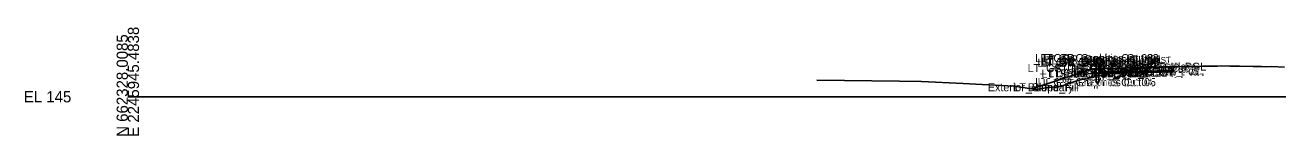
# Model space of a CAD drawing. Extents: x -26 to 603, y -10 to 9526.
# Drawn here: x -25.7 to 287.5, y 2490.3 to 2517.3 of the extents above; entities that cross this region are included whole.
import ezdxf

# ---------------------------------------------------------------- set-up
doc = ezdxf.new("R2010")
doc.units = 0
for name, color, linetype in [('Default', 7, 'Continuous'), ('Exist Cross Section Cell', 7, 'Continuous'), ('Exist XS Ground Line', 7, 'Continuous'), ('Prop CMT Guardrail Graphics', 7, 'Continuous'), ('Prop CMT Pvmt Course 1', 7, 'Continuous'), ('Prop CMT Pvmt Course 2', 7, 'Continuous'), ('Prop CMT Pvmt Course 3', 7, 'Continuous'), ('Prop CMT Pvmt Surface', 7, 'Continuous'), ('Prop CMT Pvmt Surface Shoulder', 7, 'Continuous'), ('Prop CMT Shld Paved Course 1', 7, 'Continuous'), ('Prop CMT Shld Paved Course 2', 7, 'Continuous'), ('Prop CMT Shld Paved Course 3', 7, 'Continuous'), ('Prop CMT Slope Grass', 7, 'Continuous'), ('Prop CMT Subgrade Earthwork', 7, 'Continuous'), ('Prop XS SE Text', 7, 'Continuous'), ('Prop XS Side Slope Text', 7, 'Continuous'), ('Scratch_Level_2', 7, 'Continuous')]:
    doc.layers.add(name, color=color, linetype=linetype)

msp = doc.modelspace()

# ---------------------------------------------------------------- linework, layer by layer
at = {"layer": 'Exist Cross Section Cell'}
msp.add_line((0, 2500), (300, 2500), dxfattribs=at)
at = {"layer": 'Exist XS Ground Line'}
for p, q in [((244.74, 2505.65), (252.04, 2507.04)), ((252.04, 2507.04), (252.56, 2507.07)), ((252.56, 2507.07), (253.09, 2507.09)), ((253.09, 2507.09), (254.92, 2507.17)), ((254.92, 2507.17), (255.92, 2507.22)), ((255.92, 2507.22), (258.43, 2507.35)), ((258.43, 2507.35), (258.99, 2507.48)), ((258.99, 2507.48), (259.8, 2507.44)), ((259.8, 2507.44), (260.5, 2507.49)), ((260.5, 2507.49), (261.3, 2507.51)), ((261.3, 2507.51), (261.88, 2507.48)), ((261.88, 2507.48), (262.47, 2507.48)), ((262.47, 2507.48), (264.8, 2507.54)), ((264.8, 2507.54), (266.91, 2507.58)), ((266.91, 2507.58), (268.66, 2507.61)), ((268.66, 2507.61), (272.4, 2507.66)), ((272.4, 2507.66), (273.44, 2507.72)), ((273.44, 2507.72), (275.47, 2507.67)), ((275.47, 2507.67), (277.58, 2507.63)), ((277.58, 2507.63), (277.89, 2507.63)), ((277.89, 2507.63), (281.35, 2507.58)), ((281.35, 2507.58), (283.38, 2507.53)), ((283.38, 2507.53), (284.38, 2507.49)), ((284.38, 2507.49), (285.9, 2507.53)), ((285.9, 2507.53), (289.13, 2507.37)), ((172.28, 2504.14), (192.92, 2503.92)), ((192.92, 2503.92), (198.38, 2503.81)), ((198.38, 2503.81), (208.83, 2503.28)), ((208.83, 2503.28), (221.57, 2502.63)), ((221.57, 2502.63), (223.84, 2502.34)), ((230.07, 2502.3), (233.26, 2502.59)), ((233.26, 2502.59), (235.18, 2503.28)), ((235.18, 2503.28), (238.35, 2504.34)), ((238.35, 2504.34), (244.74, 2505.65)), ((223.84, 2502.34), (226.91, 2501.79)), ((226.91, 2501.79), (230.07, 2502.3))]:
    msp.add_line(p, q, dxfattribs=at)
at = {"layer": 'Prop CMT Guardrail Graphics'}
for points in [[(242.04, 2503.57), (242.04, 2509.57)], [(242.04, 2509.57), (243.38, 2509.57), (243.65, 2509.28)], [(243.65, 2509.28), (243.38, 2508.98)], [(243.38, 2508.98), (243.65, 2508.69)], [(243.65, 2508.69), (243.38, 2508.4), (242.71, 2508.4)], [(242.71, 2508.4), (242.71, 2503.57)], [(242.71, 2503.57), (242.04, 2503.57)]]:
    msp.add_lwpolyline(points, dxfattribs=at)
at = {"layer": 'Prop CMT Pvmt Course 1'}
for points in [[(261.3, 2507.51), (253.1, 2507.3)], [(253.1, 2507.3), (253.1, 2506.39)], [(253.1, 2506.39), (261.3, 2506.59)], [(261.3, 2506.59), (261.3, 2507.51)]]:
    msp.add_lwpolyline(points, dxfattribs=at)
at = {"layer": 'Prop CMT Pvmt Course 2'}
for points in [[(261.3, 2506.59), (253.1, 2506.39)], [(253.1, 2506.39), (253.1, 2506.05)], [(253.1, 2506.05), (261.3, 2506.26)], [(261.3, 2506.26), (261.3, 2506.59)]]:
    msp.add_lwpolyline(points, dxfattribs=at)
at = {"layer": 'Prop CMT Pvmt Course 3'}
for points in [[(261.3, 2506.26), (253.1, 2506.05)], [(253.1, 2506.05), (261.3, 2506.26)], [(253.1, 2506.05), (253.1, 2506.05)], [(261.3, 2506.26), (261.3, 2506.26)]]:
    msp.add_lwpolyline(points, dxfattribs=at)
at = {"layer": 'Prop CMT Pvmt Surface'}
msp.add_lwpolyline([(261.3, 2507.51), (253.1, 2507.3)], dxfattribs=at)
at = {"layer": 'Prop CMT Pvmt Surface Shoulder'}
msp.add_lwpolyline([(253.1, 2507.3), (243.65, 2507.07)], dxfattribs=at)
at = {"layer": 'Prop CMT Shld Paved Course 1'}
for p, q in [((243.65, 2507.07), (242.71, 2506.13)), ((253.1, 2507.3), (247.64, 2507.17))]:
    msp.add_line(p, q, dxfattribs=at)
for points in [[(246.7, 2506.23), (253.1, 2506.39)], [(253.1, 2506.39), (253.1, 2507.3)]]:
    msp.add_lwpolyline(points, dxfattribs=at)
at = {"layer": 'Prop CMT Shld Paved Course 2'}
for p, q in [((242.71, 2506.13), (242.37, 2505.79)), ((253.1, 2506.39), (242.71, 2506.13))]:
    msp.add_line(p, q, dxfattribs=at)
for points in [[(246.36, 2505.89), (253.1, 2506.05)], [(253.1, 2506.05), (253.1, 2506.39)]]:
    msp.add_lwpolyline(points, dxfattribs=at)
at = {"layer": 'Prop CMT Shld Paved Course 3'}
for points in [[(253.1, 2506.05), (246.36, 2505.89), (245.86, 2505.87)], [(245.86, 2505.87), (253.1, 2506.05)], [(245.86, 2505.87), (245.86, 2505.87)], [(253.1, 2506.05), (253.1, 2506.05)]]:
    msp.add_lwpolyline(points, dxfattribs=at)
at = {"layer": 'Prop CMT Slope Grass'}
for points in [[(240.65, 2506.83), (226.02, 2501.95)], [(243.65, 2507.07), (240.65, 2506.83)]]:
    msp.add_lwpolyline(points, dxfattribs=at)
at = {"layer": 'Prop CMT Subgrade Earthwork'}
for points in [[(245.86, 2505.87), (237.13, 2505.65)], [(253.1, 2506.05), (245.86, 2505.87)], [(261.3, 2506.26), (253.1, 2506.05)]]:
    msp.add_lwpolyline(points, dxfattribs=at)

# ---------------------------------------------------------------- texts
at = {"layer": 'Default'}
msp.add_text('-', height=0.0001, dxfattribs=at).set_placement((0, 2500))
msp.add_text('-', height=0.0001, dxfattribs=at).set_placement((0, 2500))
msp.add_text('-', height=0.0001, dxfattribs=at).set_placement((0, 2500))
msp.add_text('-', height=0.0001, dxfattribs=at).set_placement((0, 2500))
at = {"layer": 'Exist Cross Section Cell'}
for s, p in [('N 662328.0085', (0, 2490)), ('E 2245945.4838', (2.8, 2490))]:
    msp.add_text(s, height=2.8, rotation=90, dxfattribs=at).set_placement(p)
msp.add_text('EL 145', height=2.8, dxfattribs=at).set_placement((-26, 2498.6))
at = {"layer": 'Prop XS SE Text'}
msp.add_text('EXIST', height=1.5, rotation=1.4321, dxfattribs=at).set_placement((254.98, 2508.35))
at = {"layer": 'Prop XS Side Slope Text'}
msp.add_text('3:1', height=1.5, rotation=18.4332, dxfattribs=at).set_placement((233.03, 2504.93))
at = {"layer": 'Scratch_Level_2'}
for s, p in [('LT_GR_Graphics Out 03', (226.78, 2508.65)), ('LT_GR_Graphics Out 06', (227.4, 2507.49)), ('LT_GR_Graphics Out 02', (228.11, 2508.65)), ('LT_GR_Graphics Out 09', (228.11, 2508.07)), ('LT_GR_Graphics Out 07', (228.11, 2507.49)), ('LT_GR_Graphics Out 08', (228.38, 2507.78)), ('LT_GR_Graphics Out 01', (228.95, 2508.36)), ('LT_GS_OS_GR_Face_Graphics', (224.94, 2506.15)), ('LT_Sub_OSS_DLT', (228.4, 2504.75)), ('LT_Sub_Trench_Out', (230.07, 2504.87)), ('LT_PS3_Shelf_Out', (231.85, 2504.87)), ('LT_GS_OS_CTL', (233.85, 2505.91)), ('LT_PS3_OEOP', (236.6, 2504.89)), ('LT_PS2_OEOP', (236.94, 2505.23)), ('LT_PS1_OEOP', (238.45, 2506.17)), ('LT_Sub_OEOT', (243.17, 2505.05)), ('LT_PV2_OEOT', (243.27, 2505.39)), ('LT_PV3_OEOT', (243.27, 2505.05)), ('LT_PV1_OEOT', (243.84, 2506.3)), ('Exterior Boundary', (245.44, 2506.51)), ('LT_Sub_PGL', (252.41, 2505.26)), ('LT_PV2_PGL', (252.51, 2505.59)), ('LT_PV3_PGL', (252.51, 2505.26)), ('LT_PV1_PGL', (253.08, 2506.51)), ('Exterior Boundary', (215.01, 2501.38)), ('LT_Slope_Fill', (221.39, 2501.38)), ('LT_GR_Graphics Out 04', (226.78, 2502.65)), ('LT_GR_Graphics Out 05', (227.44, 2502.65))]:
    msp.add_text(s, height=2, dxfattribs=at).set_placement(p)

doc.saveas('drawing.dxf')
